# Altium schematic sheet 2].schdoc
size 750 x 215 mm
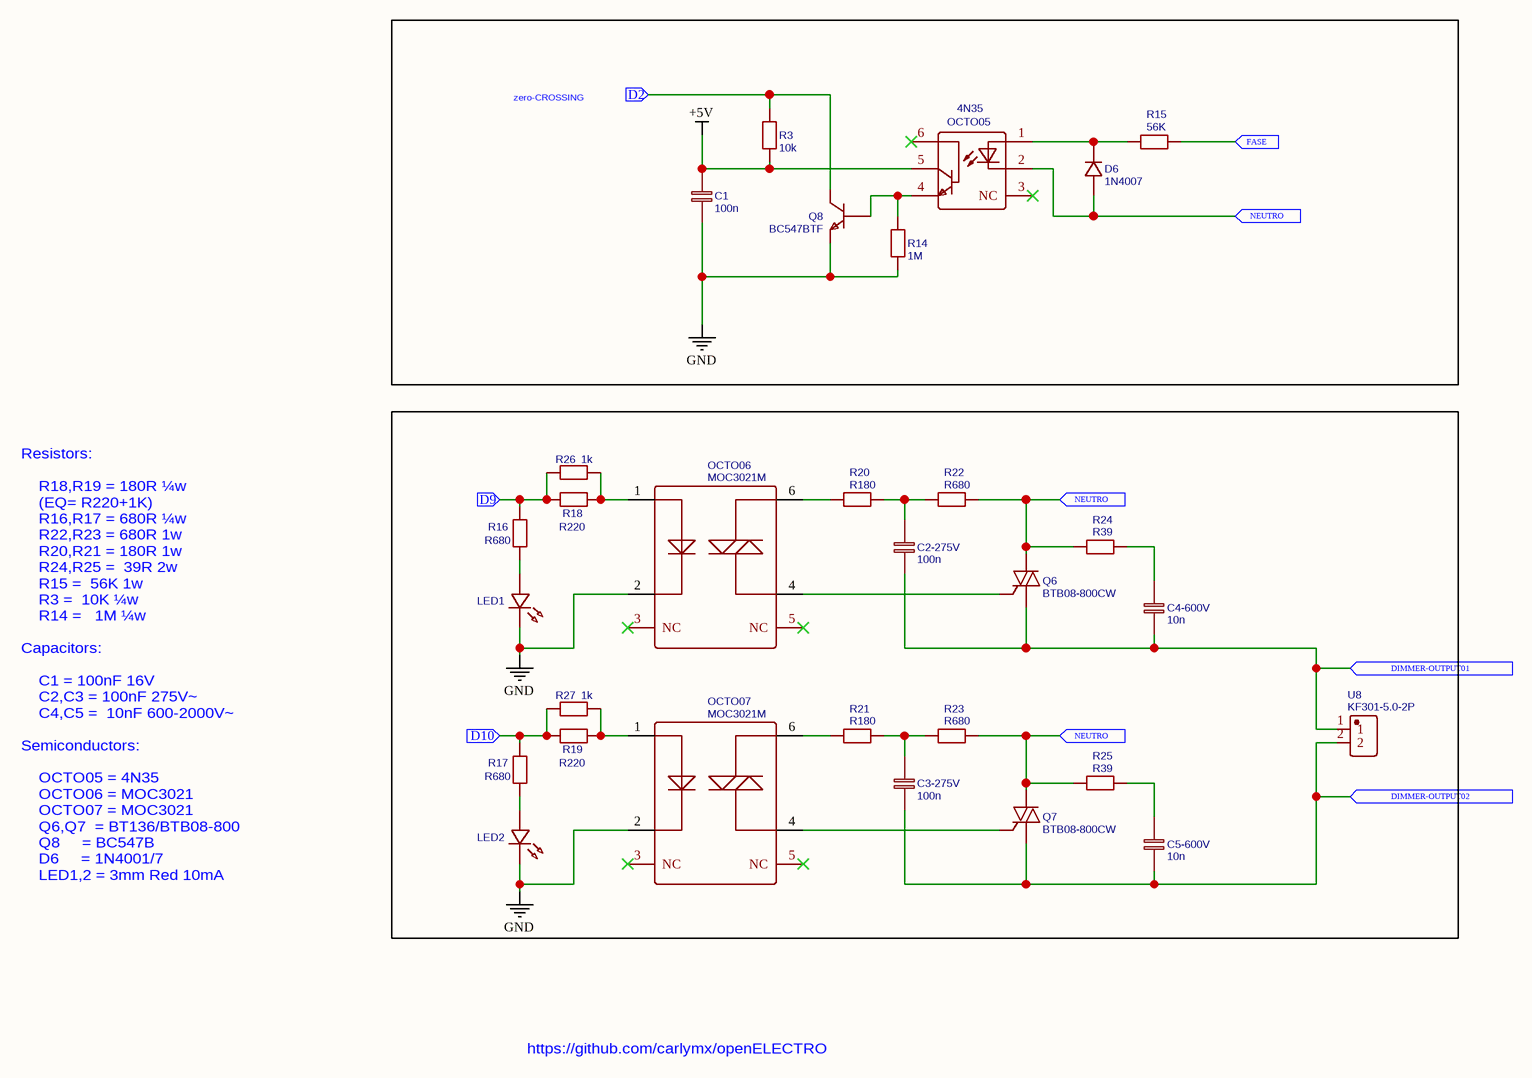
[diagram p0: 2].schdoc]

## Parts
C1  100n  [RAD-0.1]
C2-275V  100n  [RAD-0.3]
C3-275V  100n  [RAD-0.3]
C4-600V  10n  [470NF1000V]
C5-600V  10n  [470NF1000V]
D6  1N4007  [DO-41_BD2.4-L4.7-P8.70-D0.9-RD]
LED1  LED-TH-3mm_R  [LED-TH_BD3.0_RED]  (value not drawn)
LED2  LED-TH-3mm_R  [LED-TH_BD3.0_RED]  (value not drawn)
OCTO05  4N35  [DIP-6_L8.5-W6.4-P2.54-LS7.6-BL]
OCTO06  MOC3021M  [DIP-6_L7.3-W6.5-P2.54-LS7.6-BL]
OCTO07  MOC3021M  [DIP-6_L7.3-W6.5-P2.54-LS7.6-BL]
Q6  BTB08-800CW  [TO-220-3_L10.2-W4.5-P2.54-L]
Q7  BTB08-800CW  [TO-220-3_L10.2-W4.5-P2.54-L]
Q8  BC547BTF  [TO-92-3_L4.9-W3.7-P2.54-L]
R3  10k  [R_AXIAL-0.3]
R14  1M  [R_AXIAL-0.3]
R15  56K  [R_AXIAL-0.5]
R16  R680  [R_AXIAL-0.3]
R17  R680  [R_AXIAL-0.3]
R18  R220  [R_AXIAL-0.3]
R19  R220  [R_AXIAL-0.3]
R20  R180  [R_AXIAL-0.5]
R21  R180  [R_AXIAL-0.5]
R22  R680  [R_AXIAL-0.5]
R23  R680  [R_AXIAL-0.5]
R24  R39  [R_AXIAL-0.5]
R25  R39  [R_AXIAL-0.5]
R26  1k  [R_AXIAL-0.3]
R27  1k  [R_AXIAL-0.3]
U8  KF301-5.0-2P  [CONN-TH_P5.00_KF301-5.0-2P]

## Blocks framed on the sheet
zero-CROSSING: C1 D6 OCTO05 Q8 R3 R14 R15

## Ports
D2 (in), D9 (in), D10 (in), DIMMER-OUTPUT01 (in), DIMMER-OUTPUT02 (in), FASE (in), NEUTRO (in)

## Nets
+5V: C1.2 OCTO05.5 R3.1
GND: C1.1 LED1.2 LED2.2 OCTO06.2 OCTO07.2 Q8.3(E) R14.1
D2: Q8.1(C) R3.2 ; port D2
D9: R16.2 R18.1 R26.1 ; port D9
D10: R17.2 R19.1 R27.1 ; port D10
DIMMER-OUTPUT01: C2-275V.1 C4-600V.1 Q6.1(T1) U8.1 ; port DIMMER-OUTPUT01
DIMMER-OUTPUT02: C3-275V.1 C5-600V.1 Q7.1(T1) U8.2 ; port DIMMER-OUTPUT02
FASE: R15.2 ; port FASE
NEUTRO: D6.2 OCTO05.2 Q6.2(T2) Q7.2(T2) R22.2 R23.2 R24.1 R25.1 ; port NEUTRO
NetC2-275V_2: C2-275V.2 R20.2 R22.1
NetC3-275V_2: C3-275V.2 R21.2 R23.1
NetC4-600V_2: C4-600V.2 R24.2
NetC5-600V_2: C5-600V.2 R25.2
NetD6_1: D6.1 OCTO05.1 R15.1
NetLED1_1: LED1.1 R16.1
NetLED2_1: LED2.1 R17.1
NetOCTO05_4: OCTO05.4 Q8.2(B) R14.2
NetOCTO06_1: OCTO06.1 R18.2 R26.2
NetOCTO06_4: OCTO06.4 Q6.3(G)
NetOCTO06_6: OCTO06.6 R20.1
NetOCTO07_1: OCTO07.1 R19.2 R27.2
NetOCTO07_4: OCTO07.4 Q7.3(G)
NetOCTO07_6: OCTO07.6 R21.1

Not connected (* = marked no-connect by the designer): OCTO05 3(NC)* 6*; OCTO06 3(NC)* 5(NC)*; OCTO07 3(NC)* 5(NC)*

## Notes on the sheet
- Resistors:
  R18,R19 = 180R ¼w
  (EQ= R220+1K)
  R16,R17 = 680R ¼w
  R22,R23 = 680R 1w
  R20,R21 = 180R 1w
  R24,R25 =  39R 2w
  R15 =  56K 1w
  R3 =  10K ¼w
  R14 =   1M ¼w
  Capacitors:
  C1 = 100nF 16V
  C2,C3 = 100nF 275V~
  C4,C5 =  10nF 600-2000V~
  Semiconductors:
  OCTO05 = 4N35
  OCTO06 = MOC3021
  OCTO07 = MOC3021
  Q6,Q7  = BT136/BTB08-800
  Q8     = BC547B
  D6     = 1N4001/7
  LED1,2 = 3mm Red 10mA
- https://github.com/carlymx/openELECTRO

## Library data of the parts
C1 C2-275V C3-275V = 100n: nameAlias: Value(F); Contributor: LCEDA_Lib
C4-600V C5-600V = 10n: nameAlias: Value(F); Contributor: LCEDA_Lib
D6 = 1N4007: BOM_Manufacturer: SEMTECH; Contributor: LCEDA_Lib
LED1 LED2 = LED-TH-3mm_R: BOM_Manufacturer: EVERLIGHT(台湾亿光); BOM_Manufacturer Part: 204-10SDRD/S530-A3-L; Contributor: LCEDA_Lib
OCTO05 = 4N35: BOM_Manufacturer: EVERLIGHT
OCTO06 OCTO07 = MOC3021M: BOM_Manufacturer: FAIRCHILD
Q6 Q7 = BTB08-800CW: BOM_Manufacturer: WEIDA(韦达); Contributor: LCSC
Q8 = BC547BTF: BOM_Manufacturer: ON(安森美); Contributor: LCSC
R3 = 10k: nameAlias: Value(Ω); Contributor: LCEDA_Lib
R14 = 1M: nameAlias: Value(Ω); Contributor: LCEDA_Lib
R15 = 56K: nameAlias: Value(Ω); Contributor: LCEDA_Lib
R16 R17 R22 R23 = R680: nameAlias: Value(Ω); Contributor: LCEDA_Lib
R18 R19 = R220: nameAlias: Value(Ω); Contributor: LCEDA_Lib
R20 R21 = R180: nameAlias: Value(Ω); Contributor: LCEDA_Lib
R24 R25 = R39: nameAlias: Value(Ω); Contributor: LCEDA_Lib
R26 R27 = 1k: nameAlias: Value(Ω); Contributor: LCEDA_Lib
U8 = KF301-5.0-2P: BOM_Manufacturer: Cixi Kefa Elec; Contributor: LCSC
